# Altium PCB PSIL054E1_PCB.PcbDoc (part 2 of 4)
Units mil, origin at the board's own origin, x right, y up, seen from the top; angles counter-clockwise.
Board outline 2080 x 2700 mil, 8 copper layers (SSTXRX1, GND Plane 1, High Speed, GND Plane 2, Power 1, Power 2, GND Plane 3, SSTXRX2), stack 58.12 mil thick; 247 components, 148 nets, 834 pads, 632 vias.
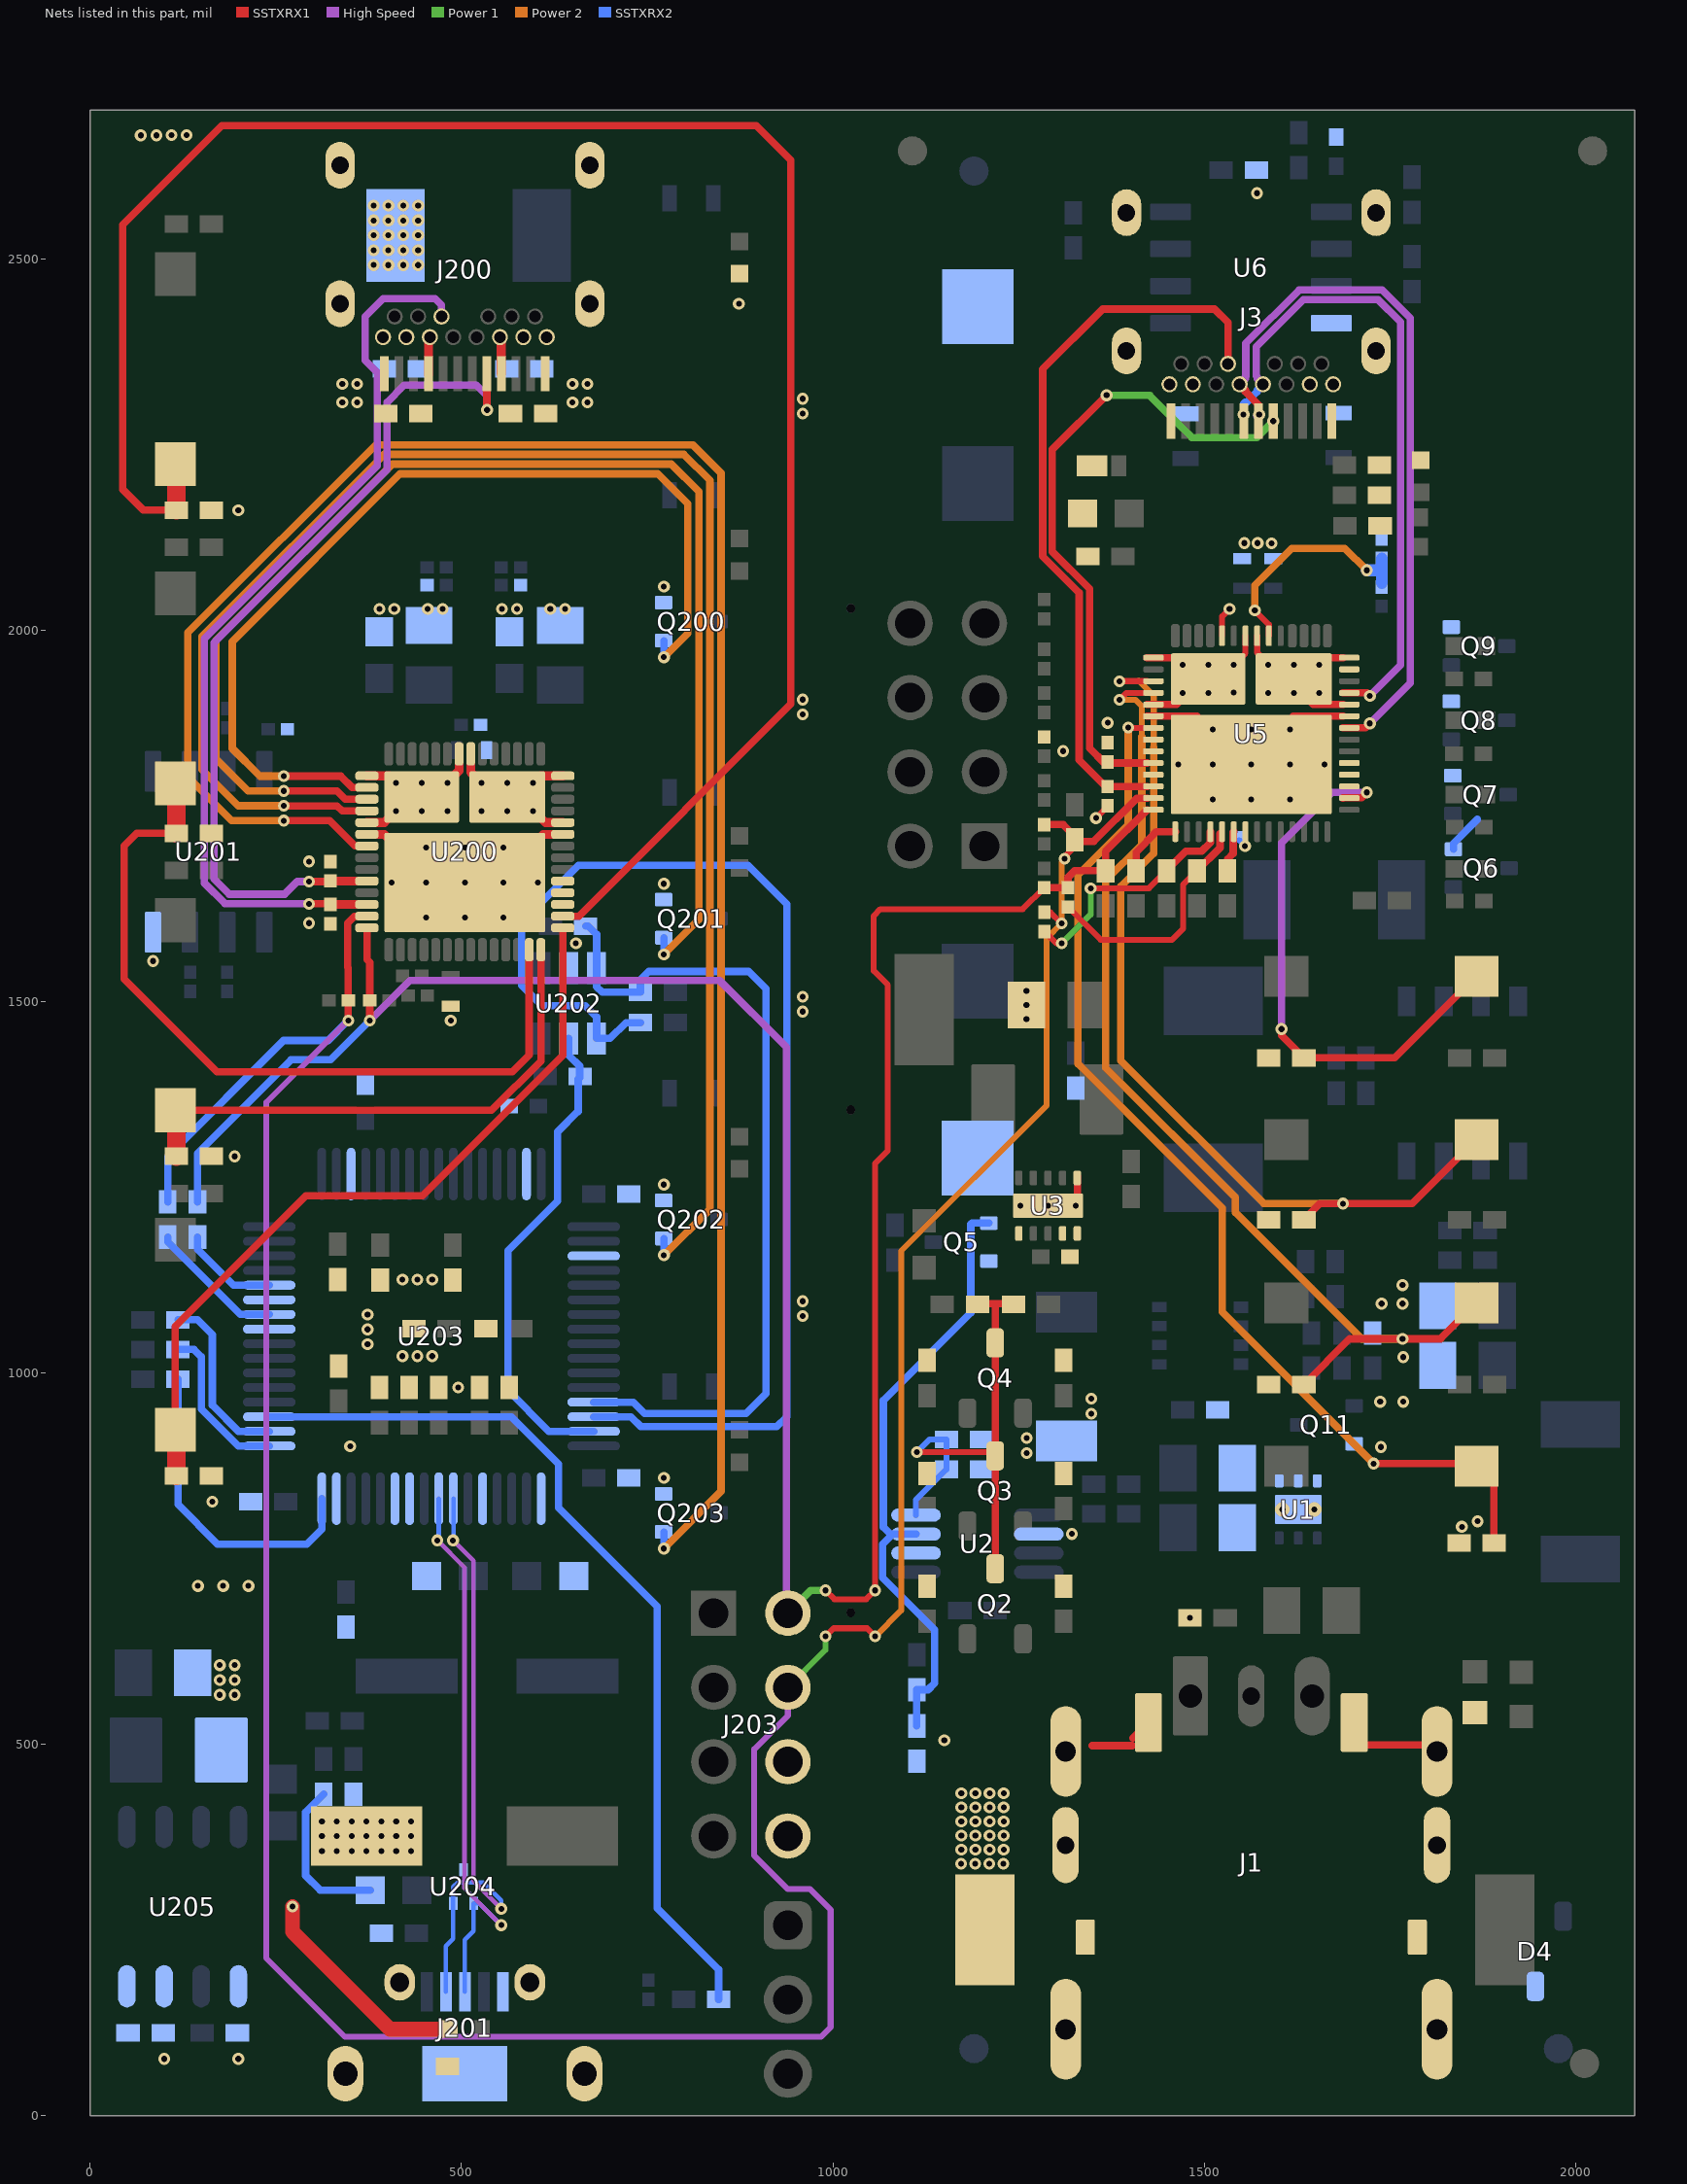
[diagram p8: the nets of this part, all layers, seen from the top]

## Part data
C1 C2: "CAP, TA, 47 µF, 35 V, +/- 20%, 0.9 ohm, AEC-Q200 Grade 1, SMD", Cap_Case=7343-43, Manufacturer=AVX, Supplier Part Number 1=478-3958-1-ND, Tolerance_%=20, Value1="0.9 ohm", Value2=35V, ValueDisplayed=47µF
C3 C4 C12 C13: "CAP, CERM, 22 µF, 35 V, +/- 20%, X5R, 0805", Cap_Case=0805, Manufacturer=TDK, Supplier Part Number 1=445-14428-1-ND, TempCo=X5R, Tolerance_%=20, Value1=Unknown, Value2=35V, ValueDisplayed=22µF
C5: "CAP, CERM, 0.1 µF, 50 V, +/- 10%, X7R, 0402", Cap_Case=0402, Manufacturer=TDK, Supplier Part Number 1=445-5932-1-ND, TempCo=X7R, Tolerance_%=10, Value1=Unknown, Value2=50V, ValueDisplayed=0.1µF
C6 C9: "CAP, CERM, 1000 pF, 50 V,+/- 20%, X7R, 0402", Cap_Case=0402, Manufacturer=TDK, Supplier Part Number 1=445-173775-1-ND, TempCo=X7R, Tolerance_%=20, Value2=50V, ValueDisplayed=1000pF
C7: "CAP, CERM, 0.1 µF, 35 V, +/- 10%, X5R, 0402", Cap_Case=0402, Manufacturer="Taiyo Yuden", Supplier Part Number 1=587-1994-1-ND, TempCo=X5R, Tolerance_%=10, Value1=Unknown, Value2=35V, ValueDisplayed=0.1µF
C8: "CAP, CERM, 100 pF, 50 V,+/- 10%, X7R, 0402", Cap_Case=0402, Manufacturer="Yageo America", Supplier Part Number 1=311-1419-1-ND, TempCo=X7R, Tolerance_%=10, Value2=50V, ValueDisplayed=100pF
C10: library part CMP-0006283-2, "CAP, CERM, 2.2 uF, 35 V, +/- 10%, X5R, 0402", Cap_Case=0402_065, Manufacturer=TDK, Supplier Part Number 1=445-9028-1-ND, TempCo=X5R, Tolerance_%=10%, Value1="0.005925 ohm", Value2=35V, ValueDisplayed=2.2uF
C11: "CAP, CERM, 47 µF, 6.3 V, +/- 20%, X5R, 0805", Cap_Case=0805, Manufacturer=MuRata, Supplier Part Number 1=490-9960-1-ND, TempCo=X5R, Tolerance_%=20, Value1=Unknown, Value2=6.3V, ValueDisplayed=47µF
C14: "CAP, CERM, 0.1 µF, 35 V,+/- 10%, X5R, 0402", Cap_Case=0402, Manufacturer="Taiyo Yuden", Supplier Part Number 1=587-1994-1-ND, TempCo=X5R, Tolerance_%=10, Value2=35V, ValueDisplayed=0.1µF
C15 C16: "CAP, CERM, 0.1 µF, 25 V,+/- 10%, X7R, 0402", Cap_Case=0402, Manufacturer=MuRata, Supplier Part Number 1=490-10698-1-ND, TempCo=X7R, Tolerance_%=10, Value2=25V, ValueDisplayed=0.1µF
C18 C19: "CAP, CERM, 220 pF, 25 V, +/- 10%, X7R, 0201", Cap_Case=0201, Manufacturer=MuRata, Supplier Part Number 1=490-3176-1-ND, TempCo=X7R, Tolerance_%=10, Value1=Unknown, Value2=25V, ValueDisplayed=220pF
C20: "CAP, CERM, 0.1 µF, 16 V,+/- 10%, X7R, 0402", Cap_Case=0402, Manufacturer="Wurth Elektronik", Supplier Part Number 1=732-7532-1-ND, TempCo=X7R, Tolerance_%=10, Value2=16V, ValueDisplayed=0.1µF
C21: "CAP, CERM, 1 µF, 50 V,+/- 10%, X7R, 0603", Cap_Case=0603, Manufacturer="Taiyo Yuden", Supplier Part Number 1=587-3247-1-ND, TempCo=X7R, Tolerance_%=10, Value2=50V, ValueDisplayed=1µF
C22 C23 C26: "CAP, CERM, 10 µF, 10 V, +/- 20%, X5R, 0402", Cap_Case=0402, Manufacturer="Samsung Electro-Mechanics", TempCo=X5R, Tolerance_%=20, Value1=Unknown, Value2=10V, ValueDisplayed=10µF
C24 C25: "CAP, CERM, 10 µF, 25 V, +/- 20%, X5R, 0603", Cap_Case=0603, Manufacturer=MuRata, Supplier Part Number 1=490-7202-1-ND, TempCo=X5R, Tolerance_%=20, Value1=Unknown, Value2=25V, ValueDisplayed=10µF
C27 C28 C29 C30: library part CMP-0006674-2, "CAP, CERM, 0.01 uF, 50 V, +/- 10%, X7R, 0402", Cap_Case=0402, Manufacturer=MuRata, Supplier Part Number 1=490-4516-1-ND, TempCo=X7R, Tolerance_%=10%, Value1=Unknown, Value2=50V, ValueDisplayed=0.01uF
C200 C201: library part CMP-0007350-5, "CAP, CERM, 1 uF, 50 V, +/- 10%, X5R, 0603", Cap_Case=0603, Manufacturer=MuRata, Supplier Part Number 1=13T1194, TempCo=X5R, Tolerance_%=10%, Value1=Unknown, Value2=50V, ValueDisplayed=1uF
C202 C203 C204 C205: library part CMP-0006356-2, "CAP, CERM, 0.1 uF, 50 V, +/- 10%, X7R, AEC-Q200 Grade 1, 0402", Cap_Case=0402, Manufacturer=MuRata, Supplier Part Number 1=490-10672-1-ND, TempCo=X7R, Tolerance_%=10%, Value1=Unknown, Value2=50V, ValueDisplayed=0.1uF
C206 C207: library part CMP-0074692-1, "CAP, CERM, 10 µF, 10 V,+/- 20%, X5R, 0402", Cap_Case=0402, Manufacturer=MuRata, TempCo=X5R, Tolerance_%=20%, Value2=10V, ValueDisplayed=10µF
C208 C213: library part CMP-0009719-2, "CAP, CERM, 0.1 uF, 25 V, +/- 10%, X5R, 0201", Cap_Case=0201, Manufacturer=MuRata, Supplier Part Number 1=GRM033R61E104KE14D-ND, TempCo=X5R, Tolerance_%=10%, Value1=Unknown, Value2=25V, ValueDisplayed=0.1uF
C209 C210 C231: library part CMP-0007842-2, "CAP, CERM, 10 uF, 35 V, +/- 10%, X5R, 0805", Cap_Case=0805, Manufacturer=TDK, Supplier Part Number 1=445-14417-1-ND, TempCo=X5R, Tolerance_%=10%, Value1="0.002818 ohm", Value2=35V, ValueDisplayed=10uF
C211 C212: library part CMP-0009770-1, "CAP, CERM, 220 pF, 25 V, +/- 10%, X7R, 0201", Cap_Case=0201, Manufacturer=MuRata, Supplier Part Number 1=490-3176-1-ND, TempCo=X7R, Tolerance_%=10%, Value1=Unknown, Value2=25V, ValueDisplayed=220pF
C214 C216 C217 C219 C220 C221 C222 C223 C224 C225 C230: library part CMP-0006297-1, "CAP, CERM, 0.1 uF, 50 V, +/- 10%, X7R, 0402", Cap_Case=0402, Manufacturer=TDK, Supplier Part Number 1=445-5932-1-ND, TempCo=X7R, Tolerance_%=10%, Value1="0.039064 ohm", Value2=50V, ValueDisplayed=0.1uF
C215 C218 C226: library part CMP-0006269-2, "CAP, CERM, 4.7 uF, 10 V, +/- 20%, X5R, 0402", Cap_Case=0402, Manufacturer=TDK, Supplier Part Number 1=445-8023-1-ND, TempCo=X5R, Tolerance_%=20%, Value1=Unknown, Value2=10V, ValueDisplayed=4.7uF
C227 C229: library part CMP-0007116-4, "CAP, CERM, 27 pF, 50 V, +/- 1%, C0G/NP0, 0603", Cap_Case=0603, Manufacturer="Samsung Electro-Mechanics", TempCo=C0G/NP0, Tolerance_%=1%, Value1=Unknown, Value2=50V, ValueDisplayed=27pF
C228: library part CMP-0006236-2, "CAP, CERM, 0.01 uF, 50 V, +/- 5%, X7R, 0402", Cap_Case=0402, Manufacturer=Kemet, Supplier Part Number 1=399-7758-1-ND, TempCo=X7R, Tolerance_%=5%, Value1=Unknown, Value2=50V, ValueDisplayed=0.01uF
C232: library part CMP-0011512-2, "CAP, TA, 10 uF, 10 V, +/- 10%, 2.5 ohm, SMD", Cap_Case=B, Manufacturer=Vishay-Sprague, Supplier Part Number 1=718-1122-1-ND, Tolerance_%=10%, Value1="2.5 ohm", Value2=10V, ValueDisplayed=10uF
D1: library part CMP-0077825-1, "Diode, Schottky, 40 V, 5 A, AEC-Q101, SOD-128", Manufacturer=Nexperia, Supplier Part Number 1=1727-5842-1-ND, Value1=5A, Value2=.49V
D2: library part CMP-0002938-2, "LED, Blue, SMD", Color=Blue, Manufacturer=Lite-On, Power_TotalModule=76mW, Supplier Part Number 1=160-1827-1-ND, Value1=0.076W, Value2=2.8V
D3: "LED, Green, SMD", Color=Green, Manufacturer="Wurth Elektronik", Supplier Part Number 1=732-4971-1-ND, Value1=W, Value2=3.2V
D4: library part CMP-0079048-1, "Diode, TVS, Uni, 24 V, 70 Vc, SOT-23", Manufacturer=Nexperia, Supplier Part Number 1=1727-3823-1-ND
D5 D6 D7 D8 D9 D200 D201 D202 D203 D204: "LED, White, SMD", Color=White, Manufacturer=OSRAM, Supplier Part Number 1="LW QH8G-Q2S2-3K5L-1-ND", Value1=W, Value2=2.8V
D10: library part CMP-0028829-1, "Diode, Schottky, 30 V, 2 A, 2-XFDFN", Manufacturer="ON Semiconductor", Supplier Part Number 1=NSR20F30NXT5GOSCT-ND, Value1=2A, Value2=0.48V
D205: library part CMP-0002919-1, "LED, White, SMD", Color=White, Manufacturer=OSRAM, Supplier Part Number 1="LW QH8G-Q2S2-3K5L-1-ND", Value1=W, Value2=2.8V
F200: library part CMP-0003604-2, "Fuse, 15 A, SMD", Irating_A=15A, Manufacturer="Bel Fuse", Supplier Part Number 1=507-1059-1-ND
FID1 FID2 FID3: "Fiducial mark.  There is nothing to buy or mount.", Manufacturer=N/A
FID4 FID5 FID6: library part CMP-0077181-1, "Fiducial mark.  There is nothing to buy or mount.", Manufacturer=N/A
J1: library part CMP-0081194-3, "Connector, DC Power Jack, R/A, 3 Pos, Gold, TH", Color=Black, Current_A=10A, Manufacturer=Foxconn
J2: "Receptacle, 2.54mm, 4x2, Gold, TH", Color=Black, Current_A=6.3, Manufacturer=Samtec, Supplier Part Number 1=SAM1196-04-ND
J3 J200: library part CMP-0080891-1, "Connector, Receptacle, USB Type C, R/A", Color=Black, Current_A=3A, Manufacturer="Wurth Elektronik", Supplier Part Number 1=732-9618-1-ND, Voltage_V=5V
J201: library part CMP-0075126-1, "Connector, Receptacle, Micro-USB Type AB, R/A, Bottom Mount SMT", Alternate PartNumber=ZX62RD-AB-5P8(30), Manufacturer="Hirose Electric Co. Ltd.", Supplier Part Number 1=H11611CT-ND
J202: library part CMP-0075407-2, "Header, 100mil, 3x1, Gold, TH", Color=Black, Current_A=6.3A, Manufacturer=Samtec, Supplier Part Number 1=SAM1029-03-ND, Voltage_V=550V
J203: library part CMP-0055685-1, "Receptacle, 2.54mm, 4x2, Gold, TH", Color=Black, Current_A=6.3A, Manufacturer=Samtec, Supplier Part Number 1=SAM1196-04-ND
L1: library part CMP-0059579-1, "Inductor, Wirewound, 10 uH, 4 A, 0.068 ohm, SMD", Manufacturer="Abracon Corporation", Supplier Part Number 1=ASPI-0630LR-100M-T15CT-ND, Value1="0.068 ohm", Value2=4A, ValueDisplayed=10uH
L2: library part CMP-0064080-1, "Inductor, Shielded Drum Core, Powdered Iron, 10 uH, 1.5 A, 0.215 ohm, SMD", Manufacturer="Wurth Elektronik", Supplier Part Number 1=732-3336-1-ND, Value1="0.215 ohm", Value2=1.5A, ValueDisplayed=10uH
L200: library part CMP-0003354-2, "Ferrite Bead, 26 ohm @ 100 MHz, 6 A, 0603", Manufacturer=MuRata, Supplier Part Number 1=490-3995-1-ND, Value1="0.007 ohm", Value2=6A, ValueDisplayed="26 ohm"
Logo200: library part CMP-0074844-1
Logo203: library part CMP-0074769-1
Logo?: library part CMP-0074847-1, "FCC_disclaimer"
Q1: library part CMP-0000004-2, "MOSFET, P-CH, -30 V, -11 A, FET, 3x0.8x3mm", Alternate Manufacturer=None, Manufacturer=AOS, Supplier Part Number 1=785-1303-1-ND, Value2="18 nC"
Q2 Q3 Q4: "MOSFET, N-CH, 20 V, 1.05 A, SOT-23", Alternate Manufacturer=None, Manufacturer="NXP Semiconductor", Supplier Part Number 1=568-6215-1-ND, Value1="0.2 ohm", Value2="3.9 nC"
Q5 Q6 Q7 Q8 Q9: "MOSFET, N-CH, 30 V, 0.18 A, SOT-323", Alternate Manufacturer=None, Manufacturer="NXP Semiconductor", Supplier Part Number 1=568-10508-1-ND, Value1="5.2 ohm", Value2="0.34 nC"
Q10: library part CMP-0000129-2, "MOSFET, 2-CH, P-CH, -30 V, -60 A, 610x604x515mm", Alternate Manufacturer=None, Manufacturer=Vishay-Siliconix, Supplier Part Number 1=SI7997DP-T1-GE3CT-ND, Value1=0.007, Value2="51 nC"
Q11: "MOSFET, N-CH, 30 V, 0.35 A, AEC-Q101, SOT-323", Alternate Manufacturer=None, Manufacturer="NXP Semiconductor", Supplier Part Number 1=568-10498-1-ND, Value1="1.4 ohm", Value2="0.52 nC"
Q200 Q201 Q202 Q203: library part CMP-0000757-1, "MOSFET, N-CH, 50 V, 0.2 A, SOT-323", Alternate Manufacturer=None, Manufacturer="Diodes Inc.", Supplier Part Number 1=BSS138W-FDICT-ND, Value1=3
R1: "RES, 0, 5%, 0.125 W, 0805", Manufacturer=Panasonic, Power_W=0.125, Supplier Part Number 1=P0.0ACT-ND, TempCo="600 ppm/C", Tolerance_%=5, Value1=5%, Value2=0.125W, Value_Code=0000, ValueDisplayed=0
R2 R5 R11 R12 R13 R32: "RES, 100 k, 1%, 0.063 W, 0402", Manufacturer=Vishay-Dale, Power_W=0.063, Supplier Part Number 1=541-100KLCT-ND, TempCo="100 ppm/C", Tolerance_%=1, Value1=1%, Value2=0.063W, Value_Code=100k
R3: "RES, 47.5 k, 1%, 0.063 W, 0402", Manufacturer=Vishay-Dale, Power_W=0.063, Supplier Part Number 1=541-47.5KLCT-ND, TempCo="100 ppm/C", Tolerance_%=1, Value1=1%, Value2=0.063W, Value_Code=47k5, ValueDisplayed=47.5k
R4: "RES, 30 k, 5%, 0.063 W, 0402", Manufacturer=Vishay-Dale, Power_W=0.063, Supplier Part Number 1=541-30KJCT-ND, TempCo="200 ppm/C", Tolerance_%=5, Value1=5%, Value2=0.063W, Value_Code=30k0, ValueDisplayed=30k
R6: "RES, 270, 5%, 0.063 W, 0402", Manufacturer=Vishay-Dale, Power_W=0.063, Supplier Part Number 1=541-270JCT-ND, TempCo="200 ppm/C", Tolerance_%=5, Value1=5%, Value2=0.063W, Value_Code=270R, ValueDisplayed=270
R7: "RES, 10 k, 5%, 0.1 W, 0603", Manufacturer="Yageo America", Power_W=0.1, Supplier Part Number 1=311-10KGRCT-ND, TempCo="100 ppm/C", Tolerance_%=5, Value1=5%, Value2=0.1W, Value_Code=10k0, ValueDisplayed=10k
R8 R18 R19 R20 R21 R24 R25 R26 R27 R38 R44 R61: "RES, 10.0 k, 1%, 0.1 W, 0402", Manufacturer=Panasonic, Power_W=0.1, Supplier Part Number 1=P10.0KLCT-ND, TempCo="100 ppm/C", Tolerance_%=1, Value1=1%, Value2=0.1W, Value_Code=10k0, ValueDisplayed=10.0k
R9: "RES, 11.0 k, 1%, 0.063 W, 0402", Manufacturer=Vishay-Dale, Power_W=0.063, Supplier Part Number 1=541-11.0KLCT-ND, TempCo="100 ppm/C", Tolerance_%=1, Value1=1%, Value2=0.063W, Value_Code=11k0, ValueDisplayed=11.0k
R10: "RES, 9.53 k, 1%, 0.063 W, 0402", Manufacturer=Vishay-Dale, Power_W=0.063, Supplier Part Number 1=541-9.53KLCT-ND, TempCo="100 ppm/C", Tolerance_%=1, Value1=1%, Value2=0.063W, Value_Code=9k53, ValueDisplayed=9.53k
R14: "RES, 8.87 k, 1%, 0.063 W, 0402", Manufacturer=Vishay-Dale, Power_W=0.063, Supplier Part Number 1=541-8.87KLCT-ND, TempCo="100 ppm/C", Tolerance_%=1, Value1=1%, Value2=0.063W, Value_Code=8k87, ValueDisplayed=8.87k
R15: "RES, 3.65 k, 1%, 0.063 W, 0402", Manufacturer=Vishay-Dale, Power_W=0.063, Supplier Part Number 1=541-3.65KLCT-ND, TempCo="100 ppm/C", Tolerance_%=1, Value1=1%, Value2=0.063W, Value_Code=3k65, ValueDisplayed=3.65k
R16: "RES, 2.20 k, 1%, 0.063 W, 0402", Manufacturer=Vishay-Dale, Power_W=0.063, Supplier Part Number 1=541-2.20KLCT-ND, TempCo="100 ppm/C", Tolerance_%=1, Value1=1%, Value2=0.063W, Value_Code=2k20, ValueDisplayed=2.20k
R17: library part CMP-0025950-3, "RES, 100 k, 1%, 0.063 W, AEC-Q200 Grade 0, 0402", Manufacturer=Vishay-Dale, Power_W=63mW, Supplier Part Number 1=541-100KLCT-ND, TempCo="100 ppm/C", Tolerance_%=1%, Value2=0.063W, Value_Code=100k
R22 R23: library part CMP-0016044-3, "RES, 0, 5%, 0.75 W, AEC-Q200 Grade 0, 2010", Manufacturer=Vishay-Dale, Power_W=750mW, Supplier Part Number 1=541-0.0WCT-ND, TempCo=ppm/C, Tolerance_%=5%, Value2=0.75W, Value_Code=0000, ValueDisplayed=0
R31: "RES, 1.00 k, 1%, 0.1 W, 0402", Manufacturer=Panasonic, Power_W=0.1, Supplier Part Number 1=P1.00KLCT-ND, TempCo="100 ppm/C", Tolerance_%=1, Value1=1%, Value2=0.1W, Value_Code=1k00, ValueDisplayed=1.00k
R36 R37 R46: "RES, 3.83 k, 1%, 0.063 W, 0402", Manufacturer=Vishay-Dale, Power_W=0.063, Supplier Part Number 1=541-3.83KLCT-ND, TempCo="100 ppm/C", Tolerance_%=1, Value1=1%, Value2=0.063W, Value_Code=3k83, ValueDisplayed=3.83k
R39 R40 R41 R42: "RES, 3.3 k, 5%, 0.063 W, 0402", Manufacturer=Vishay-Dale, Power_W=0.063, Supplier Part Number 1=541-3.3KJCT-ND, TempCo="200 ppm/C", Tolerance_%=5, Value1=5%, Value2=0.063W, Value_Code=3k30, ValueDisplayed=3.3k
R43: "RES, 0, 5%, 0.063 W, 0402", Manufacturer="Yageo America", Power_W=0.063, Supplier Part Number 1=311-0.0JRCT-ND, TempCo="200 ppm/C", Tolerance_%=5, Value1=5%, Value2=0.063W, Value_Code=0000, ValueDisplayed=0
R45: library part CMP-0026339-2, "RES, 3.83 k, 1%, 0.063 W, AEC-Q200 Grade 0, 0402", Manufacturer=Vishay-Dale, Power_W=63mW, Supplier Part Number 1=541-3.83KLCT-ND, TempCo="100 ppm/C", Tolerance_%=1%, Value2=0.063W, Value_Code=3k83, ValueDisplayed=3.83k
R47: library part CMP-0027262-3, "RES, 10.0 k, 1%, 0.05 W, 0201", Manufacturer=Vishay-Dale, Power_W=50mW, Supplier Part Number 1=541-10.0KAABCT-ND, TempCo="100 ppm/C", Tolerance_%=1%, Value2=0.05W, Value_Code=10k0, ValueDisplayed=10.0k
R48 R49 R50 R51 R53 R54 R55 R56 R57: library part CMP-0027008-4, "RES, 0, 5%, 0.05 W, 0201", Manufacturer=Vishay-Dale, Power_W=50mW, Supplier Part Number 1=72M6743, TempCo=ppm/C, Tolerance_%=5%, Value2=0.05W, Value_Code=0000, ValueDisplayed=0
R52: library part CMP-0027261-3, "RES, 100 k, 1%, 0.05 W, 0201", Manufacturer=Vishay-Dale, Power_W=50mW, Supplier Part Number 1=541-100KAABCT-ND, TempCo="100 ppm/C", Tolerance_%=1%, Value2=0.05W, Value_Code=100k
R58 R60 R63 R65 R215 R217 R219 R223: library part CMP-0081856-1, "RES, 0, 0%, 0.2 W, AEC-Q200 Grade 0, 0402", Manufacturer=Vishay-Dale, Power_W=200mW, Supplier Part Number 1=541-0.0YBTR-ND, Tolerance_%=0%, Value2=0.2W, Value_Code=0
R59 R62 R64 R66 R216 R218 R222 R224: library part CMP-0026768-2, "RES, 100 k, 0.5%, 0.063 W, AEC-Q200 Grade 0, 0402", Manufacturer=Vishay-Dale, Power_W=63mW, Supplier Part Number 1=541-100KAVCT-ND, TempCo="50 ppm/C", Tolerance_%=0.5%, Value2=0.063W, Value_Code=100k
R200 R213 R214 R220 R221: library part CMP-0025686-1, "RES, 10.0 k, 0.1%, 0.1 W, AEC-Q200 Grade 1, 0603", Manufacturer=Vishay-Dale, Power_W=100mW, Supplier Part Number 1=TNP10.0KAACT-ND, TempCo="25 ppm/C", Tolerance_%=0.1%, Value2=0.1W, Value_Code=10k0, ValueDisplayed=10.0k
R201 R202 R203 R204: library part CMP-0027277-3, "RES, 3.83 k, 1%, 0.05 W, 0201", Manufacturer=Vishay-Dale, Power_W=50mW, Supplier Part Number 1=541-3.83KAABCT-ND, TempCo="100 ppm/C", Tolerance_%=1%, Value2=0.05W, Value_Code=3k83, ValueDisplayed=3.83k
R205 R206 R207 R208: library part CMP-0027656-1, "RES, 3.32 k, 1%, 0.05 W, 0201", Manufacturer="Yageo America", Power_W=50mW, Supplier Part Number 1=YAG2340CT-ND, TempCo="200 ppm/C", Tolerance_%=1%, Value2=0.05W, Value_Code=3k32, ValueDisplayed=3.32k
R209: library part CMP-0027414-1, "RES, 191 k, 1%, 0.05 W, 0201", Manufacturer="Yageo America", Power_W=50mW, Supplier Part Number 1=YAG2460CT-ND, TempCo="200 ppm/C", Tolerance_%=1%, Value2=0.05W, Value_Code=191k
R210: library part CMP-0027291-2, "RES, 10.0 k, 1%, 0.05 W, 0201", Manufacturer=Rohm, Power_W=50mW, Supplier Part Number 1=RHM10KCBCT-ND, TempCo="250 ppm/C", Tolerance_%=1%, Value2=0.05W, Value_Code=10k0, ValueDisplayed=10.0k
R211 R212: library part CMP-0027943-1, "RES, 100 k, 1%, 0.05 W, 0201", Manufacturer="Yageo America", Power_W=50mW, Supplier Part Number 1=603-RC0201FR-7D100KL, TempCo="200 ppm/C", Tolerance_%=1%, Value2=0.05W, Value_Code=100k
R225 R226 R227 R234 R235: library part CMP-0026658-1, "RES, 10.0 k, 1%, 0.1 W, 0402", Manufacturer=Panasonic, Power_W=100mW, Supplier Part Number 1=P10.0KLCT-ND, TempCo="100 ppm/C", Tolerance_%=1%, Value2=0.1W, Value_Code=10k0, ValueDisplayed=10.0k
R228: library part CMP-0026729-1, "RES, 2.20 k, 1%, 0.063 W, 0402", Manufacturer="Yageo America", Power_W=63mW, Supplier Part Number 1=311-2.20KLRCT-ND, TempCo="100 ppm/C", Tolerance_%=1%, Value2=0.063W, Value_Code=2k20, ValueDisplayed=2.20k
R229: library part CMP-0026834-2, "RES, 12 k, 5%, 0.063 W, 0402", Manufacturer=Vishay-Dale, Power_W=63mW, Supplier Part Number 1=541-12KJCT-ND, TempCo="200 ppm/C", Tolerance_%=5%, Value2=0.063W, Value_Code=12k0, ValueDisplayed=12k
R230: library part CMP-0026700-1, "RES, 4.70 k, 1%, 0.1 W, 0402", Manufacturer=Panasonic, Power_W=100mW, Supplier Part Number 1=P4.70KLCT-ND, TempCo="100 ppm/C", Tolerance_%=1%, Value2=0.1W, Value_Code=4k70, ValueDisplayed=4.70k
R231 R233 R236 R237 R238 R239 R240 R241 R243 R244: library part CMP-0026822-3, "RES, 0, 5%, 0.063 W, AEC-Q200 Grade 0, 0402", Manufacturer=Vishay-Dale, Power_W=63mW, Supplier Part Number 1=541-0.0JCT-ND, TempCo="200 ppm/C", Tolerance_%=5%, Value2=0.063W, Value_Code=0000, ValueDisplayed=0
R232: library part CMP-0026657-1, "RES, 1.00 k, 1%, 0.1 W, 0402", Manufacturer=Panasonic, Power_W=100mW, Supplier Part Number 1=P1.00KLCT-ND, TempCo="100 ppm/C", Tolerance_%=1%, Value2=0.1W, Value_Code=1k00, ValueDisplayed=1.00k
R242: library part CMP-0022234-4, "RES, 249 k, 1%, 0.1 W, AEC-Q200 Grade 0, 0603", Manufacturer=Vishay-Dale, Power_W=100mW, Supplier Part Number 1=541-249KHCT-ND, TempCo="100 ppm/C", Tolerance_%=1%, Value2=0.1W, Value_Code=249k
S1 S2 S3 S4 S200 S201 S202 S203: library part CMP-0002196-2, "Switch, Tactile, SPST, 12 V, SMD", CurrentRating_mA=50A, Manufacturer="Wurth Elektronik", Supplier Part Number 1=31T8978
SH-J1: library part CMP-0003761-2, "Shunt, 2.54mm, Gold, Black", Manufacturer="Wurth Elektronik", Supplier Part Number 1=732-2678-ND
TP1 TP2 TP3: library part 5019, "Test Point, Miniature, SMT", Manufacturer=Keystone, Supplier Part Number 1=5019KCT-ND
TP200 TP201: library part CMP-0055162-1, "Test Point, Miniature, SMT", Manufacturer=Keystone, Supplier Part Number 1=36-5019TR-ND
U1: library part CMP-0077834-1, "22-V Precision Surge Protection Clamp, DRV0006A (WSON-6)", Alternate Manufacturer="Texas Instruments"
U2: "Hysteretic PFET Buck Controller with Enable Pin, 8-pin MSOP, Pb-Free", Manufacturer="Texas Instruments", PackageTopMarking=ZXTT*STEB, PowerWise=N, Supplier Part Number 1=LM3489QMMTR-ND
U3: library part CMP-0067107-3, "28V, 0.5A Step-Down Converter with SNOOZE Mode, DQC0010A (WSON-10)", Alternate Manufacturer="Texas Instruments", Alternate PartNumber=TPS62177DQCT
U5 U200: library part CMP-0081032-2, "USB Type-C and USB PD Controller with Integrated Power Switches, RSH0056E (VQFN-56)", Alternate Manufacturer="Texas Instruments", Alternate PartNumber=TPS65987DDHRSHT
U6 U201: library part CMP-0078948-1, "8Mb, 86MHz, NOR Flash, SOP-8", Manufacturer="Macronix International Co., LTD", Supplier Part Number 1=1092-1117-ND
U202: library part CMP-0005250-2, "2K Microwire Compatible Serial EEPROM, SOT-23-6", Manufacturer=Microchip
U203: library part CMP-0004747-1, "Quad High Speed USB to Multipurpose UART/MPSSE IC", Manufacturer=FTDI, Supplier Part Number 1=768-1026-1-ND
U204: library part CMP-0043102-2, "ESD Protection Array for High-Speed Data Interfaces, 2 Channels, -40 to +85 degC, 3-pin SOT (DRT), Green (RoHS & no Sb/Br)", Breakdown Voltage(Min)(V)=9, Differential Capacitance(pF)=0.01, IO Capacitance(Typ)(pF)=0.7, IO Leakage Current(nA)=10, Manufacturer="Texas Instruments"
U205: library part CMP-0036484-1, "Single Output Fast Transient Response LDO, 1 A, Fixed 3.3 V Output, 2.7 to 10 V Input, with Low IQ, 8-pin SOIC (D), -40 to 125 degC, Green (RoHS & no Sb/Br)", Manufacturer="Texas Instruments", Power Good=TRUE
Y200: library part CMP-0004584-3, "CRYSTAL, 12 MHz, 20pF, SMD", Frequency_Fixed=12MHz, Frequency Stability=+/-50ppm, Manufacturer="ECS Inc.", Supplier Part Number 1=XC1770CT-ND
ZZ2: library part CMP-0077236-1
ZZ3: library part CMP-0077237-1
ZZ4: library part CMP-0077238-1

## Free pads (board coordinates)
  round 12 hole 12: 3(1024,677) 3(1024,1354) 3(1024,2029)

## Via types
v1: diameter 16, hole 8, SSTXRX1 to SSTXRX2, tented both sides, 581 vias
v2: diameter 19.68, hole 7.87, SSTXRX1 to SSTXRX2, tented both sides, 51 vias

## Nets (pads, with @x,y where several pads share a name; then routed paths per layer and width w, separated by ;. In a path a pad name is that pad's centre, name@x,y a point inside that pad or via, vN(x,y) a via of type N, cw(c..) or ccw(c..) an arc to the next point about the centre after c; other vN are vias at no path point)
5V_LED: Q200.1 U200.16 | length 1312
  SSTXRX1 w10: v1@260.58,1803.18 337.58,1803.18 352.83,1787.92 U200.16@372.56,1787.92
  Power 2 w10: v1(260.45,1803.31) 228.45,1803.31 191.22,1840.54 191.22,1984.08 417.45,2210.31 764.07,2210.31 804.45,2169.93 804.45,1995.31 v1(772.45,1963.31)
  SSTXRX2 w10: v1(772.45,1963.31) Q200.1@772.45,1985.31
5V_PB: R59.2 S1.1 U5.44 | length 758.5
  SSTXRX1 w10: v1(1604.13,1462.68) 1604.13,1454.08 R59.2@1634.28,1423.93 1756.61,1423.93 S1.1@1866.61,1533.93 ; U5.44@1686.99,1773.65 1686.99,1774.26 1712.1,1774.26 v1(1719.1,1781.26)
  High Speed w10: v1(1604.13,1462.68) 1604.13,1713.29 1672.1,1781.26 v1(1719.1,1781.26)
5V_PB_SINK: R216.2 S200.1 U200.44 | length 2632.8
  SSTXRX1 w10: R216.2@115.83,2161.31 71.45,2161.31 43.45,2189.31 43.45,2545.31 177.14,2679 896.75,2679 943.45,2632.31 943.45,1900.31 657.83,1614.69 U200.44@636.34,1614.69
  SSTXRX1 w25: R216.2@115.83,2161.31 S200.1@115.83,2221.98
9V_LED: Q201.1 U200.17 | length 1813.1
  SSTXRX1 w10: v1@260.58,1783.18 332.44,1783.18 343.44,1772.17 U200.17@372.56,1772.17
  Power 2 w10: v1(260.45,1783.31) 212.45,1783.31 169.45,1826.31 169.45,1985.92 406.83,2223.31 782.45,2223.31 819.45,2186.31 819.45,1610.31 v1(772.45,1563.31)
  SSTXRX2 w10: v1(772.45,1563.31) Q201.1@772.45,1585.31
9V_PB: R62.2 S2.1 U5.17 | length 1256.6
  SSTXRX1 w8: v1@1386.23,1931.13 U5.17@1423.21,1931.13
  SSTXRX1 w10: R62.2@1634.28,1205.93 1656.03,1227.68 v1(1686.91,1227.68) 1780.36,1227.68 S2.1@1866.61,1313.93
  Power 2 w8: v1(1386,1931) 1411.07,1931 1411.71,1931.65 1432.1,1911.26 1432.1,1842.26
  Power 2 w10: 1387.66,1654.82 1387.66,1420.34 1580.32,1227.68 v1(1686.91,1227.68) ; 1388.1,1655.26 1432.1,1699.26 1432.1,1842.26
9V_PB_SINK: R218.2 S201.1 U200.41 | length 1070.3
  SSTXRX1 w10: R218.2@115.83,1726.31 62.45,1726.31 45.45,1709.31 45.45,1530.31 170.45,1405.31 568.45,1405.31 591.06,1427.92 U200.41@591.06,1569.42
  SSTXRX1 w25: R218.2@115.83,1726.31 S201.1@115.83,1791.98
15V_LED: Q202.1 U200.18 | length 2314.7
  SSTXRX1 w10: v1@260.58,1763.18 332.44,1763.18 339.19,1756.43 U200.18@372.56,1756.43
  Power 2 w10: v1(260.45,1763.31) 199.45,1763.31 150.45,1812.31 150.45,1991.31 395.45,2236.31 799.45,2236.31 834.45,2201.31 834.45,1220.31 v1(772.45,1158.31)
  SSTXRX2 w10: v1(772.45,1158.31) Q202.1@772.45,1180.31
15V_PB: R64.2 S3.1 U5.18 | length 1422.2
  SSTXRX1 w8: v1(1386,1906) 1395.38,1915.38 U5.18@1423.21,1915.38
  SSTXRX1 w10: R64.2@1634.28,983.93 1696.03,1045.68 v1(1767.13,1045.68) 1818.36,1045.68 S3.1@1866.61,1093.93
  Power 2 w8: v1(1386,1906) 1407.36,1906 1416.1,1897.26 1416.1,1856.26
  Power 2 w10: 1416.1,1856.26 1416.1,1711.26 1367.47,1662.63 1367.47,1410.53 1542.03,1235.97 1542.03,1215.78 1712.13,1045.68 v1(1767.13,1045.68)
15V_PB_SINK: R222.2 S202.1 U200.42 | length 730.2
  SSTXRX1 w10: S202.1@114.45,1353.35 540.49,1353.35 606.81,1419.67 U200.42@606.81,1569.42
  SSTXRX1 w25: R222.2@115.83,1291.31 S202.1@115.83,1351.98
20V_LED: Q203.1 U200.21 | length 2813.9
  SSTXRX1 w10: v1@260.58,1743.18 322.58,1743.18 356.57,1709.18 U200.21@372.56,1709.18
  Power 2 w10: v1(260.45,1743.31) 190.45,1743.31 131.45,1802.31 131.45,1996.31 384.45,2249.31 811.45,2249.31 849.45,2211.31 849.45,840.31 v1(772.45,763.31)
  SSTXRX2 w10: v1(772.45,763.31) Q203.1@772.45,785.31
20V_PB: R66.2 S4.1 U5.21 | length 1461.7
  SSTXRX1 w8: v1@1398.22,1868.14 U5.21@1423.21,1868.14
  SSTXRX1 w10: v1(1728.13,877.68) 1862.86,877.68 S4.1@1866.61,873.93 1890.28,850.26 R66.2@1890.28,770.93
  Power 2 w10: v1(1397.71,1868.65) 1397.71,1737.71 1330,1670 1330,1416 1524.13,1221.87 1524.13,1081.68 v1(1728.13,877.68)
20V_PB_SINK: R224.2 S203.1 U200.43 | length 1044.3
  SSTXRX1 w10: S203.1@114.27,923.53 114.36,923.62 114.36,1062.22 290.45,1238.31 447.45,1238.31 636.34,1427.2 U200.43@636.34,1598.94
  SSTXRX1 w25: R224.2@115.83,861.31 S203.1@115.83,921.98
/PGOOD: U5.55
ADCIN1: R47.1 R52.2 U5.6 | length 311.9
  SSTXRX1 w8: v1(1568.1,2026.26) 1587.12,2007.24 U5.6@1587.12,1992.15
  Power 2 w10: v1(1568.1,2026.26) 1568.1,2060.26 1617.85,2110.01 1689.41,2110.01 v1(1719.1,2080.32)
  SSTXRX2 w16: v1(1719.1,2080.32) 1738.1,2080.32 ; R47.1@1739.1,2063.31 R52.2@1739.1,2096.32
C_USB_N: J3.A7 J3.B7 U5.53 | length 902.1
  SSTXRX1 w10: U5.53@1686.99,1915.38 U5.53@1695.39,1915.38 1706.35,1915.38 1706.47,1915.26 1719.1,1915.26 v1(1723.1,1911.26)
  High Speed w10: v1@1553,2287.06 v1(1553,2290) ; J3.B7@1579.25,2330.75 1571.58,2338.42 1571.58,2340.62 1570,2342.2 1570,2381.5 1633.5,2445 1734,2445 1764.57,2414.43 1764.57,1952.73 v1(1723.1,1911.26)
  SSTXRX2 w10: v1(1553,2290) 1553,2304.5 1555.42,2306.92 1557.62,2306.92 1571.58,2320.88 1571.58,2323.08 J3.B7@1579.25,2330.75
C_USB_P: J3.A6 J3.B6 U5.50 | length 996.7
  SSTXRX1 w10: J3.B6@1547.75,2330.75 1555.42,2323.08 1555.42,2320.88 1569.38,2306.92 1569.38,2306.62 1573.34,2302.66 J3.A6@1573.34,2281.14 ; U5.50@1686.99,1868.14 U5.50@1695.39,1868.14 1706.34,1868.14 1706.47,1868.26 1717.1,1868.26 v1(1723.1,1874.26)
  High Speed w10: J3.B6@1547.75,2330.75 1555.42,2338.42 1555.42,2340.62 1556,2341.2 1556,2385.88 1628.12,2458 1739.38,2458 1777.57,2419.81 1777.57,1928.73 v1(1723.1,1874.26) ; v1@1570.84,2288.16 1572.68,2290 v1(1574,2290)
CC1: C18.1 J3.A5 U5.24 | length 869.2
  SSTXRX1 w10: v1(1368.57,2316.01) 1295.49,2242.93 1295.49,2105.51 1345.57,2055.43 1345.57,1841.01 1365.69,1820.89 U5.24@1423.21,1820.89
  Power 1 w10: v1(1368.57,2316.01) 1426.47,2316.01 1483.48,2259 1570.88,2259 v1(1593.03,2281.14)
CC1_SINK: C212.2 J200.A5 U200.24 | length 1176.6
  SSTXRX1 w10: v1(294.45,1661.31) C212.2@323.2,1661.31 ; v1@533.97,2296.78 J200.A5@533.97,2344.77
  SSTXRX1 w12: C212.2@323.83,1661.94 U200.24@372.56,1661.94
  High Speed w10: v1(294.45,1661.31) 278.9,1661.31 261.9,1644.31 186.83,1644.31 166.45,1664.69 166.45,1982.92 399.45,2215.92 399.45,2306.31 422.79,2329.65 519.92,2329.65 534.45,2315.13 v1(534.45,2296.31)
CC2: C19.1 J3.B5 U5.26 | length 998.9
  SSTXRX1 w10: U5.26@1423.21,1789.39 1367.18,1789.39 1331.57,1825.01 1331.57,2050.43 1282.49,2099.51 1282.49,2350.93 1363.57,2432.01 1513.99,2432.01 1532,2414 J3.B5@1532,2358.31
CC2_SINK: C211.2 J200.B5 U200.26 | length 1229.3
  SSTXRX1 w10: v1(294.45,1631.31) 322.46,1631.31 C211.2@323.46,1630.31
  SSTXRX1 w12: C211.2@323.59,1630.44 U200.26@372.56,1630.44
  High Speed w10: v1(294.45,1631.31) 181.45,1631.31 153.45,1659.31 153.45,1988.31 386.45,2221.31 386.45,2346.38 370,2362.83 370,2421.86 394.45,2446.31 464.45,2446.31 472.95,2437.8 J200.B5@472.95,2421.94
DRAIN1: U5.8 U5.15 U5.19 U5.58@1505.43,1934.08 | length 205.7
  SSTXRX1 w8: U5.58@1521.08,1934.08 1555.63,1968.63 U5.8@1555.63,1992.15
  SSTXRX1 w10: U5.19@1423.21,1899.63 1462.58,1899.63 U5.58@1497.03,1934.08 ; U5.15@1423.21,1962.62 U5.58@1468.48,1962.62
  other v2: 1470.98,1915.38 1505.43,1915.38 1540,1916 1470.98,1952.78 1505.43,1952.78 1539.88,1952.78
Drain1_SINK: U200.8 U200.15 U200.19 U200.58@446.38,1775.13 | length 135.1
  SSTXRX1 w12: U200.19@372.56,1740.68 395.82,1740.68 U200.58@411.45,1756.31 ; U200.15@372.56,1803.67 402.09,1803.67 v2(411.93,1793.83) U200.58@412.45,1793.31 ; U200.58@480.45,1794.31 496.57,1810.43 U200.8@496.57,1833.2
  other v2: 411.93,1756.43 446.38,1756.43 480.83,1756.43 446.38,1793.83 480.83,1793.83
DRAIN2: U5.7 U5.52 U5.56 U5.57@1620.59,1934.08 | length 245
  SSTXRX1 w8: U5.7@1571.37,1992.15 1571.37,1969.63 U5.57@1606.92,1934.08
  SSTXRX1 w10: U5.57@1606.92,1934.08 1612.18,1934.08 1646.63,1899.63 U5.52@1686.99,1899.63 ; U5.57@1616.39,1938.28 U5.57@1638.76,1960.65 ; U5.57@1640.73,1962.62 U5.56@1686.99,1962.62
  other v2: 1586.14,1915.38 1620.59,1915.38 1655.04,1915.38 1586.14,1952.78 1620.59,1952.78 1655.04,1952.78
Drain2_SINK: U200.7 U200.52 U200.56 U200.57@561.53,1775.13 | length 135.7
  SSTXRX1 w12: U200.7@512.32,1833.2 512.32,1808.43 U200.57@526.45,1794.31 ; U200.57@596.45,1757.31 613.08,1740.68 U200.52@636.34,1740.68 ; U200.57@596.45,1793.31 606.81,1803.67 U200.56@636.34,1803.67
  other v2: 527.09,1756.43 561.53,1756.43 595.98,1756.43 527.09,1793.83 561.53,1793.83 595.98,1793.83
EECLK: R227.1 U202.4 U203.62 | length 1671.9
  SSTXRX2 w10: U203.62@677.95,940.72 728.04,940.72 741.45,927.31 924.45,927.31 938,940.86 938,1630.75 885.45,1683.31 657.45,1683.31 581,1606.86 581,1521.75 608.45,1494.31 666.45,1494.31 681.85,1478.91 U202.4@681.85,1450.06 700.06,1450.06 721.31,1471.31 R227.1@740.83,1471.31
EECS: R226.1 U202.5 U203.63 | length 658.2
  SSTXRX2 w10: U202.5@644.45,1450.06 644.45,1427.55 659,1413 659,1397.38 657,1395.38 657,1351.86 629.45,1324.31 629.45,1231.31 562.45,1164.31 562.45,976.31 617.72,921.03 U203.63@677.95,921.03
EEDATA: R225.1 R228.2 U202.3 U203.61 | length 1146
  SSTXRX2 w10: R228.2@667.07,1601.31 670.69,1601.31 681.85,1590.15 U202.3@681.85,1544.55 681.85,1519.91 689.45,1512.31 R225.1@740.83,1512.31 740.83,1528.69 752.45,1540.31 886.45,1540.31 910,1516.75 910,972 883.31,945.31 746.45,945.31 731.35,960.4 U203.61@677.95,960.4
EN_VAR: Q5.1 R5.1 R9.2 U2.3 | length 839.5
  SSTXRX2 w10: U2.3@1081,783 U2.3@1080.73,782.73 ; U2.3@1111.98,782.73 U2.3@1080.73,782.73 ; R9.2@1113,524.41 R5.1@1113,573.17 1128.17,573.17 1137,582 1137,654 1067,724 1067,769 U2.3@1080.73,782.73 ; 1185.66,1199.93 1185.66,1080.66 1068,963 1068,792 1077.27,782.73 U2.3@1080.73,782.73 ; 1187.25,1201.52 Q5.1@1210.06,1201.52
F_I2C1_SCL: R241.1 U203.26 | length 183.4
  SSTXRX2 w10: R241.1@104.45,1182.69 104.45,1176.31 202.24,1078.51 U203.26@240.94,1078.51
F_I2C1_SDA: R243.1 U203.27 U203.28 | length 132.9
  SSTXRX2 w10: R243.1@144.45,1182.69 144.45,1166.31 192.87,1117.88 U203.28@240.94,1117.88
F_SPI_CLK: R237.1 U203.16 | length 433.7
  SSTXRX2 w10: R237.1@118.07,991.31 118.07,822.69 171.45,769.31 291.45,769.31 311.81,789.67 U203.16@311.81,830.48
F_SPI_CSZ: R240.1 U203.19 | length 1226.1
  SSTXRX2 w10: U203.19@240.94,940.72 567.04,940.72 630.45,877.31 630.45,818.31 763.45,685.31 763.45,279.31 846.07,196.69 R240.1@846.07,156.31
F_SPI_MISO: R239.1 U203.18 | length 240.8
  SSTXRX2 w10: R239.1@118.07,1071.31 144.45,1071.31 164.45,1051.31 164.45,956.31 199.72,921.03 U203.18@240.94,921.03
F_SPI_MOSI: R238.1 U203.17 | length 217.7
  SSTXRX2 w10: R238.1@118.07,1031.31 139.45,1031.31 149.45,1021.31 149.45,951.31 199.41,901.35 U203.17@240.94,901.35
F_USB_D_N: J201.2 U203.7 U204.2 | length 813.3
  High Speed w6: v1(488.45,774.31) 516,746.75 516,315.75 v1(553.45,278.31)
  SSTXRX2 w6: J201.2@478.86,166.54 478.86,227.86 488.67,237.67 U204.2@488.67,285.67 488.67,307.67 495,314 529,314 553.45,289.55 v1(553.45,278.31) ; v1(488.45,774.31) 488.97,774.83 U203.7@488.97,830.48
F_USB_D_P: J201.3 U203.8 U204.1 | length 783.9
  High Speed w6: v1(467.45,774.31) 504,737.75 504,305.75 v1(553.45,256.31)
  SSTXRX2 w6: v1(467.45,774.31) 469.29,776.15 U203.8@469.29,830.48 ; J201.3@504.45,166.54 504.45,236.45 516.23,248.23 U204.1@516.23,285.67 524.09,285.67 v1(553.45,256.31)
F_VBUS: C230.1 D205.1 L200.2 R230.2 U205.3 U205.4 | length 513.5
  SSTXRX1 w20: v1(272.45,281.31) 272.45,247.31 403.45,116.31 D205.1@482.79,116.31
  SSTXRX2 w10: R230.2@314.45,432.68 290,408.24 290,323 309.69,303.31 L200.2@376.95,303.31
"FB node on VAR_DC": C8.2 C9.1 Q2.3 Q3.3 Q4.3 R4.1 R10.2 U2.4 | length 677.6
  SSTXRX1 w8: v1(1113,893) 1213.83,893 Q3.3@1218.66,888.17
  SSTXRX1 w10: R4.1@1194.28,1092.93 1218.66,1092.93 ; Q2.3@1218.66,736.17 Q3.3@1218.66,888.17 Q4.3@1218.66,1040.17 1218.66,1092.93 ; C8.2@1242.04,1092.93 1218.66,1092.93
  SSTXRX2 w8: U2.4@1111.98,808.32 1111.98,829.06 C9.1@1152.85,869.93 R10.2@1152.85,909.93 1129.93,909.93 v1(1113,893)
FUSE_VBUS: C202.1 C203.1 C204.1 C205.1 F200.2 J200.A4 J200.A9 J200.B4 J200.B9 | length 100.6
  SSTXRX1 w10: J200.B9@551.69,2394.38 J200.B9@553.45,2392.62
  SSTXRX1 w12: J200.A9@455.45,2344.31 455.45,2392.62 J200.B4@457.2,2394.38 ; J200.A4@553.45,2345.31 J200.B9@553.45,2392.62
  other v1: 381.44,2491.31 401.45,2491.31 421.45,2491.31 441.45,2491.31 381.44,2511.31 401.45,2511.31 421.45,2511.31 441.45,2511.31 381.44,2531.31 401.45,2531.31 421.45,2531.31 441.45,2531.31 381.44,2551.31 401.45,2551.31 421.45,2551.31 441.45,2551.31 381.44,2571.31 401.45,2571.31 421.45,2571.31 441.45,2571.31
GND: C1.2 C2.2 C3.2 C4.2 C5.2 C7.2 C9.2 C10.2 C11.2 C12.2 C13.2 C18.2 C19.2 C20.2 C21.2 C22.2 C23.2 C24.2 C25.2 C26.2 C27.2 C28.2 C29.2 C30.2 C200.2 C201.2 C202.2 C203.2 C204.2 C205.2 C206.2 C207.2 C208.2 C209.2 C210.2 C211.1 C212.1 C213.2 C214.2 C215.2 C216.2 C217.1 C218.1 C219.2 C220.2 C221.2 C222.2 C223.2 C224.2 C225.2 C226.2 C227.1 C228.2 C229.1 C230.2 C231.2 C232.2 D1.2 D4.3 D9.2 D10.2 D200.2 J1.4 J1.5 J1.6 J1.7 J1.8 J1.9 J1.MP1 J1.MP2 J1.MP3 J1.MP4 J3.A1 J3.A12 J3.B1 J3.B12 J3.M1 J3.M2 J3.S1 J3.S2 J3.S3 J3.S4 J200.A1 J200.A12 J200.B1 J200.B12 J200.M1 J200.M2 J200.S1 J200.S2 J200.S3 J200.S4 J201.5 J201.6 J201.7 J201.8 J201.9 J201.10 J203.6 J203.8 Q5.2 Q6.2 Q7.2 Q8.2 Q9.2 Q11.2 Q200.2 Q201.2 Q202.2 Q203.2 R2.1 R7.1 R9.1 R10.1 R11.1 R12.1 R13.1 R14.1 R15.1 R16.1 R32.1 R43.1 R52.1 R57.1 R59.1 R62.1 R64.1 R66.1 R211.1 R212.1 R216.1 R218.1 R222.1 R224.1 R229.2 R231.2 R233.2 R234.1 R235.1 R236.2 R244.2 TP2.1 TP201.1 U1.1 U1.2 U1.3 U1.7@1626.66,815.93 U2.2 U2.6 U3.1 U3.4 U3.5 U3.6 U3.11@1289.66,1224.93 U5.10 U5.20 U5.25 U5.45 U5.46 U5.47 U5.51 U5.59@1563.5,1818.92 U6.4 U200.20 U200.45 U200.46 U200.47 U200.51 U200.59@504.45,1659.97 U201.4 U202.2 U203.1 U203.5 U203.10 U203.11 U203.15 U203.25 U203.35 U203.47 U203.51 U204.3 U205.1 | length 626.5
  SSTXRX1 w8: v1(1354.35,1746.73) 1370.1,1762.48 C19.2@1370.1,1763.27 ; U5.10@1524.13,1992.15 1524.13,2018.29 v1(1534.1,2028.26)
  SSTXRX1 w10: U3.11@1329.29,1228.9 U3.6@1329.29,1264.33 ; 1349.21,498 1403,498 ; 1404,508 J1.MP1@1425,529 ; U5.20@1423.21,1883.88 U5.59@1490.14,1883.88 ; U5.59@1620.06,1883.88 U5.51@1686.99,1883.88 ; J1.MP2@1702,529 1702,515 1718,499 1805,499 J1.7@1812,492
  SSTXRX1 w12: U200.20@372.56,1724.93 395.83,1724.93 U200.59@418.45,1702.31 ; U200.59@597.45,1712.31 610.07,1724.93 U200.51@636.34,1724.93
  SSTXRX2 w10: C22.2@1547,1762 1559.84,1762 1563.5,1765.66 v2(1563.5,1771.68) ; Q6.2@1835.7,1704.85 1835.7,1712.7 1868,1745
  other v1: 99.45,76.31 199.45,76.31 1172.66,338.93 1191.66,338.93 1210.66,338.93 1229.66,338.93 312,356 332,356 352,356 372,356 392,356 412,356 432,356 1173,358 1192,358 1211,358 1230,358 312,376 332,376 352,376 372,376 392,376 412,376 432,376 1173,377 1192,377 1211,377 1230,377 312,396 332,396 352,396 372,396 392,396 412,396 432,396 1173,396 1192,396 1211,396 1230,396 1173,415 1192,415 1211,415 1230,415 1173,434 1192,434 1211,434 1230,434 1150,505 174.45,566.31 194.45,566.31 174.45,586.31 194.45,586.31 174.45,606.31 194.45,606.31 1481.04,669.93 145,713 179,713 213,713 1322,783 1847,792.58 1868,800 164.45,826.31 772.45,858.31 1261,892 1738,900 350,901 1261,912 1348,945 1737,961 1768,961 1348,965 495.45,980.31 1768,1021 420.45,1022.31 440.45,1022.31 460.45,1022.31 373.45,1038.31 373.45,1058.31 959.45,1076.31 373.45,1078.31 1739,1093 1767,1093 959.45,1096.31 1767,1118 420.45,1125.31 440.45,1125.31 460.45,1125.31 772.45,1253.31 194.45,1291.31 485.45,1474.31 1260.66,1475.93 959.45,1486.31 1260.66,1494.93 959.45,1506.31 1260.66,1513.93 84.45,1554.31 654,1578 294.45,1605.31 772.45,1658.31 294.45,1688.31 1310,1837 1370,1875 959.45,1886.31 959.45,1906.31 389.45,2028.31 409.45,2028.31 454.45,2028.31 474.45,2028.31 554.45,2028.31 574.45,2028.31 619.45,2028.31 639.45,2028.31 772.45,2058.31 1554,2117 1572,2117 1590.9,2116.74 199.45,2161.31 959.45,2291.31 339.45,2306.31 359.45,2306.31 649.45,2306.31 669.45,2306.31 959.45,2311.31 339.45,2331.31 359.45,2331.31 649.45,2331.31 669.45,2331.31 873.45,2439.31 1571,2588 68,2666 89,2666 109.45,2666.31 129.6,2666.15
  other v2: 1605,815.93 1648.31,815.93 1252.26,1224.93 1289.66,1224.93 1327.06,1224.93 452.48,1612.72 504.45,1612.72 556.42,1612.72 406.02,1659.97 452.48,1659.97 504.45,1659.97 556.42,1659.97 602.87,1659.97 452.48,1707.21 504.45,1707.21 556.42,1707.21 1511.53,1771.68 1615.47,1771.68 1465.07,1818.92 1511.53,1818.92 1563.5,1818.92 1615.47,1818.92 1661.93,1818.92 1511.53,1866.17 1563.5,1866.17 1615.47,1866.17
GPIO_6/I2C3_SDA: U5.22
GPIO_7/I2C3_IRQZ: U5.23
I2C1_IRQZ: R38.1 U5.29 | length 89.3
  SSTXRX1 w10: R38.1@1408.29,1675.88 1408.29,1701.07 1435.59,1728.37 U5.29@1461.14,1728.37
I2C1_SCL: J203.4 R36.1 R48.2 R50.1 R201.1 R241.2 U5.27 U200.27 | length 4746.9
  SSTXRX1 w8: v1(990,645) 1001,656 1046,656 v1(1057,645) ; R48.2@1285,1619.99 1293.01,1619.99 v1(1308,1605) ; v1(1312.07,1692) 1312.07,1694.89 R36.1@1332.57,1715.39
  SSTXRX1 w10: v1(347.46,1474.3) 347.46,1501.29 347.44,1545.12 346.45,1546.11 346.45,1605.31 355.83,1614.69 U200.27@372.56,1614.69 ; R50.1@1284.57,1738 1309.96,1738 1332.57,1715.39 1351.22,1715.39 1409.48,1773.65 U5.27@1423.21,1773.65
  High Speed w8: v1(347.46,1474.3) 237,1363.84 237,212 343,106 984,106 997,119 997,277 969,305 939,305 894,350 894,493 939.45,538.45 J203.4@939.45,576.31
  Power 1 w8: J203.4@939.45,576.31 990,626.86 v1(990,645)
  Power 2 w8: v1(1057,645) 1092,680 1092,1164 1288,1360 1288,1585 v1(1308,1605) 1308,1687.93 v1(1312.07,1692)
  SSTXRX2 w10: R241.2@104.45,1229.93 104.45,1291.31 260.45,1447.31 320.46,1447.31 v1(347.46,1474.3)
I2C1_SDA: J203.2 R37.1 R49.2 R51.1 R202.1 R243.2 U5.28 U200.28 | length 3392.4
  SSTXRX1 w8: v1(990,707) 1002,695 1045,695 v1(1057,707) 1057,1282 1074,1299 1074,1522 1055,1541 1055,1615 1064,1624 1255.55,1624 R51.1@1284.57,1653.02
  SSTXRX1 w10: U200.28@372.56,1598.94 372.56,1556.2 376.46,1552.3 R202.1@376.46,1501.31 v1(376.46,1474.3) ; R51.1@1284.57,1653.02 R49.2@1316.57,1653 1316.57,1666.98 1325.48,1675.88 R37.1@1367.29,1675.88 1367.29,1701.98 U5.28@1423.21,1757.9
  High Speed w10: v1(376.46,1474.3) 430.46,1528.31 847.45,1528.31 937.45,1438.31 J203.2@937.45,678.31
  Power 1 w10: J203.2@939.45,676.31 970.14,707 v1(990,707)
  SSTXRX2 w10: R243.2@144.45,1229.93 144.45,1295.31 270.45,1421.31 323.46,1421.31 v1(376.46,1474.3)
I2C2_IRQZ: R44.2 U5.34 | length 56
  SSTXRX1 w10: R44.2@1531.29,1675.88 1531.29,1691.29 1539,1699 1539,1727.49 U5.34@1539.88,1728.37
I2C2_SCL: R46.2 R48.1 U5.32 | length 321.4
  SSTXRX1 w8: R48.1@1285,1594.01 1301.01,1578 v1(1308,1578) ; v1(1347.1,1652.26) 1425.66,1652.26 R46.2@1449.29,1675.88
  SSTXRX1 w10: R46.2@1449.29,1675.88 1475.4,1702 1496.53,1702 1508.38,1713.86 U5.32@1508.38,1728.37
  Power 1 w8: v1(1308,1578) 1347.1,1617.1 v1(1347.1,1652.26)
I2C2_SDA: R45.2 R49.1 U5.33 | length 327.9
  SSTXRX1 w8: R49.1@1316.57,1627.02 1360.59,1583 1456.84,1583 1471.48,1597.64 1471.48,1657.07 R45.2@1490.29,1675.88
  SSTXRX1 w10: R45.2@1490.29,1675.88 1521.38,1706.98 U5.33@1521.38,1725.62
LDO_1V8: C22.1 U5.35 | length 11.3
  SSTXRX2 w8: C22.1@1547,1717 v1(1555,1709)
